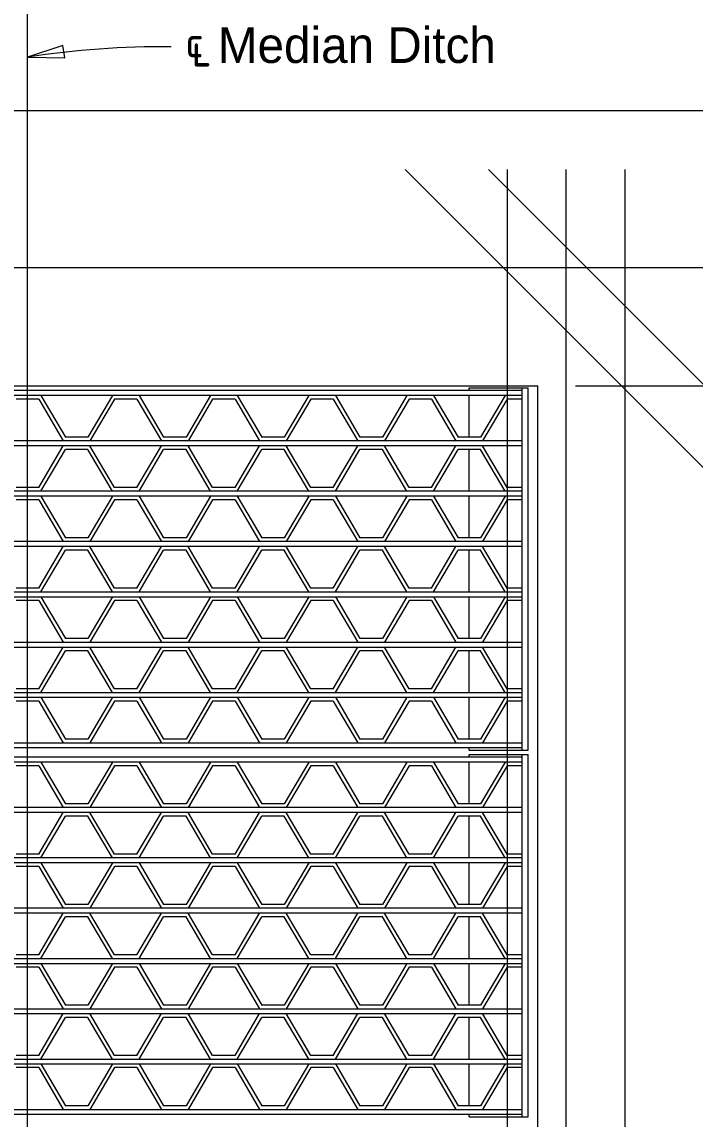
# Model space of a CAD drawing. Extents: x 1.4 to 54.1, y -0.5 to 22.6.
# Drawn here: x 17.123 to 19.98, y 12.044 to 16.698 of the extents above; entities that cross this region are included whole.
import ezdxf

# ---------------------------------------------------------------- set-up
doc = ezdxf.new("R2010")
doc.units = 0
for name, color, linetype in [('AdhocPoint_dp', 7, 'Continuous'), ('CL_Major', 7, 'Continuous'), ('Leader', 7, 'Continuous'), ('PlotBorder_dp', 7, 'Continuous'), ('Rebar', 7, 'Continuous'), ('Rebar_h', 7, 'Continuous'), ('SteelMisc', 7, 'Continuous'), ('WallConc', 7, 'Continuous'), ('WallConc_h', 7, 'Continuous')]:
    doc.layers.add(name, color=color, linetype=linetype)

msp = doc.modelspace()

# ---------------------------------------------------------------- linework, layer by layer
at = {"layer": 'CL_Major'}
msp.add_line((17.1465, 8.8184), (17.1465, 16.8163), dxfattribs=at)
at = {"layer": 'Leader'}
msp.add_arc((17.7214, 12.8798), 3.7133, 89.4708, 98.906, dxfattribs=at)
at = {"layer": 'PlotBorder_dp'}
msp.add_line((19.473, 15.1547), (22.2866, 15.1547), dxfattribs=at)
msp.add_lwpolyline([(17.1465, 16.5483), (17.3049, 16.5463), (17.2967, 16.5986)], close=True, dxfattribs=at)
at = {"layer": 'Rebar'}
for p, q in [((21.2249, 13.5966), (18.7501, 16.0714)), ((21.5785, 13.5966), (19.1036, 16.0714))]:
    msp.add_line(p, q, dxfattribs=at)
at = {"layer": 'Rebar_h'}
for p, q in [((19.1831, 9.1964), (19.1831, 16.0714)), ((19.4331, 9.1964), (19.4331, 16.0714)), ((19.6831, 9.1964), (19.6831, 16.0714))]:
    msp.add_line(p, q, dxfattribs=at)
at = {"layer": 'SteelMisc'}
for p, q in [((19.2455, 15.1346), (15.0476, 15.1346)), ((19.0215, 15.1452), (19.2715, 15.1452)), ((19.0215, 15.1346), (19.0215, 15.1452)), ((19.2455, 13.6087), (19.2455, 15.1452)), ((19.2715, 13.6087), (19.2715, 15.1452)), ((19.2455, 15.1138), (15.0476, 15.1138)), ((17.1941, 15.0982), (17.0989, 15.0982)), ((17.1941, 15.0982), (17.2983, 14.9211)), ((17.2031, 15.1138), (17.3072, 14.9367)), ((17.5067, 15.1138), (17.4025, 14.9367)), ((17.5156, 15.0982), (17.4114, 14.9211)), ((17.6108, 15.0982), (17.5156, 15.0982)), ((17.6108, 15.0982), (17.715, 14.9211)), ((17.6198, 15.1138), (17.7239, 14.9367)), ((17.9234, 15.1138), (17.8192, 14.9367)), ((17.9323, 15.0982), (17.8281, 14.9211)), ((18.0275, 15.0982), (17.9323, 15.0982)), ((18.0275, 15.0982), (18.1317, 14.9211)), ((18.0365, 15.1138), (18.1406, 14.9367)), ((18.3401, 15.1138), (18.2359, 14.9367)), ((18.349, 15.0982), (18.2448, 14.9211)), ((18.4442, 15.0982), (18.349, 15.0982)), ((18.4442, 15.0982), (18.5484, 14.9211)), ((18.4532, 15.1138), (18.5573, 14.9367)), ((18.7568, 15.1138), (18.6526, 14.9367)), ((18.7657, 15.0982), (18.6615, 14.9211)), ((18.8609, 15.0982), (18.7657, 15.0982)), ((18.8609, 15.0982), (18.9651, 14.9211)), ((18.8699, 15.1138), (18.974, 14.9367)), ((19.0215, 14.9367), (19.0215, 15.1138)), ((19.1735, 15.1138), (19.0693, 14.9367)), ((19.1824, 15.0982), (19.0782, 14.9211)), ((19.2455, 15.0982), (19.1824, 15.0982)), ((19.2455, 14.9211), (15.0476, 14.9211)), ((19.2455, 14.9003), (15.0476, 14.9003)), ((17.1941, 14.7232), (17.2983, 14.9003)), ((17.4025, 14.9367), (17.3072, 14.9367)), ((17.5156, 14.7232), (17.4114, 14.9003)), ((17.6108, 14.7232), (17.715, 14.9003)), ((17.8192, 14.9367), (17.7239, 14.9367)), ((17.9323, 14.7232), (17.8281, 14.9003)), ((18.0275, 14.7232), (18.1317, 14.9003)), ((18.2359, 14.9367), (18.1406, 14.9367)), ((18.349, 14.7232), (18.2448, 14.9003)), ((18.4442, 14.7232), (18.5484, 14.9003)), ((18.6526, 14.9367), (18.5573, 14.9367)), ((18.7657, 14.7232), (18.6615, 14.9003)), ((18.8609, 14.7232), (18.9651, 14.9003)), ((19.0693, 14.9367), (18.974, 14.9367)), ((19.1824, 14.7232), (19.0782, 14.9003)), ((17.2031, 14.7076), (17.3072, 14.8847)), ((17.4025, 14.8847), (17.3072, 14.8847)), ((17.5067, 14.7076), (17.4025, 14.8847)), ((17.6198, 14.7076), (17.7239, 14.8847)), ((17.8192, 14.8847), (17.7239, 14.8847)), ((17.9234, 14.7076), (17.8192, 14.8847)), ((18.0365, 14.7076), (18.1406, 14.8847)), ((18.2359, 14.8847), (18.1406, 14.8847)), ((18.3401, 14.7076), (18.2359, 14.8847)), ((18.4532, 14.7076), (18.5573, 14.8847)), ((18.6526, 14.8847), (18.5573, 14.8847)), ((18.7568, 14.7076), (18.6526, 14.8847)), ((18.8699, 14.7076), (18.974, 14.8847)), ((19.0693, 14.8847), (18.974, 14.8847)), ((19.0215, 14.7076), (19.0215, 14.8847)), ((19.1735, 14.7076), (19.0693, 14.8847)), ((17.1941, 14.7232), (17.0989, 14.7232)), ((17.6108, 14.7232), (17.5156, 14.7232)), ((18.0275, 14.7232), (17.9323, 14.7232)), ((18.4442, 14.7232), (18.349, 14.7232)), ((18.8609, 14.7232), (18.7657, 14.7232)), ((19.2455, 14.7232), (19.1824, 14.7232)), ((19.2455, 14.7076), (15.0476, 14.7076)), ((19.2455, 14.6868), (15.0476, 14.6868)), ((17.1941, 14.6712), (17.0989, 14.6712)), ((17.1941, 14.6712), (17.2983, 14.4941)), ((17.2031, 14.6868), (17.3072, 14.5097)), ((17.5067, 14.6868), (17.4025, 14.5097)), ((17.5156, 14.6712), (17.4114, 14.4941)), ((17.6108, 14.6712), (17.5156, 14.6712)), ((17.6108, 14.6712), (17.715, 14.4941)), ((17.6198, 14.6868), (17.7239, 14.5097)), ((17.9234, 14.6868), (17.8192, 14.5097)), ((17.9323, 14.6712), (17.8281, 14.4941)), ((18.0275, 14.6712), (17.9323, 14.6712)), ((18.0275, 14.6712), (18.1317, 14.4941)), ((18.0365, 14.6868), (18.1406, 14.5097)), ((18.3401, 14.6868), (18.2359, 14.5097)), ((18.349, 14.6712), (18.2448, 14.4941)), ((18.4442, 14.6712), (18.349, 14.6712)), ((18.4442, 14.6712), (18.5484, 14.4941)), ((18.4532, 14.6868), (18.5573, 14.5097)), ((18.7568, 14.6868), (18.6526, 14.5097)), ((18.7657, 14.6712), (18.6615, 14.4941)), ((18.8609, 14.6712), (18.7657, 14.6712)), ((18.8609, 14.6712), (18.9651, 14.4941)), ((18.8699, 14.6868), (18.974, 14.5097)), ((19.0215, 14.5097), (19.0215, 14.6868)), ((19.1735, 14.6868), (19.0693, 14.5097)), ((19.1824, 14.6712), (19.0782, 14.4941)), ((19.2455, 14.6712), (19.1824, 14.6712)), ((19.2455, 14.4941), (15.0476, 14.4941)), ((17.4025, 14.5097), (17.3072, 14.5097)), ((17.8192, 14.5097), (17.7239, 14.5097)), ((18.2359, 14.5097), (18.1406, 14.5097)), ((18.6526, 14.5097), (18.5573, 14.5097)), ((19.0693, 14.5097), (18.974, 14.5097)), ((19.2455, 14.4733), (15.0476, 14.4733)), ((17.1941, 14.2962), (17.2983, 14.4733)), ((17.2031, 14.2806), (17.3072, 14.4577)), ((17.4025, 14.4577), (17.3072, 14.4577)), ((17.5067, 14.2806), (17.4025, 14.4577)), ((17.5156, 14.2962), (17.4114, 14.4733)), ((17.6108, 14.2962), (17.715, 14.4733)), ((17.6198, 14.2806), (17.7239, 14.4577)), ((17.8192, 14.4577), (17.7239, 14.4577)), ((17.9234, 14.2806), (17.8192, 14.4577)), ((17.9323, 14.2962), (17.8281, 14.4733)), ((18.0275, 14.2962), (18.1317, 14.4733)), ((18.0365, 14.2806), (18.1406, 14.4577)), ((18.2359, 14.4577), (18.1406, 14.4577)), ((18.3401, 14.2806), (18.2359, 14.4577)), ((18.349, 14.2962), (18.2448, 14.4733)), ((18.4442, 14.2962), (18.5484, 14.4733)), ((18.4532, 14.2806), (18.5573, 14.4577)), ((18.6526, 14.4577), (18.5573, 14.4577)), ((18.7568, 14.2806), (18.6526, 14.4577)), ((18.7657, 14.2962), (18.6615, 14.4733)), ((18.8609, 14.2962), (18.9651, 14.4733)), ((18.8699, 14.2806), (18.974, 14.4577)), ((19.0693, 14.4577), (18.974, 14.4577)), ((19.0215, 14.2806), (19.0215, 14.4577)), ((19.1735, 14.2806), (19.0693, 14.4577)), ((19.1824, 14.2962), (19.0782, 14.4733)), ((17.1941, 14.2962), (17.0989, 14.2962)), ((17.6108, 14.2962), (17.5156, 14.2962)), ((18.0275, 14.2962), (17.9323, 14.2962)), ((18.4442, 14.2962), (18.349, 14.2962)), ((18.8609, 14.2962), (18.7657, 14.2962)), ((19.2455, 14.2962), (19.1824, 14.2962)), ((15.0476, 14.2806), (19.2455, 14.2806)), ((15.0476, 14.2598), (19.2455, 14.2598)), ((17.1941, 14.2442), (17.0989, 14.2442)), ((17.1941, 14.2442), (17.2983, 14.0671)), ((17.2031, 14.2598), (17.3072, 14.0827)), ((17.5067, 14.2598), (17.4025, 14.0827)), ((17.5156, 14.2442), (17.4114, 14.0671)), ((17.6108, 14.2442), (17.5156, 14.2442)), ((17.6108, 14.2442), (17.715, 14.0671)), ((17.6198, 14.2598), (17.7239, 14.0827)), ((17.9234, 14.2598), (17.8192, 14.0827)), ((17.9323, 14.2442), (17.8281, 14.0671)), ((18.0275, 14.2442), (17.9323, 14.2442)), ((18.0275, 14.2442), (18.1317, 14.0671)), ((18.0365, 14.2598), (18.1406, 14.0827)), ((18.3401, 14.2598), (18.2359, 14.0827)), ((18.349, 14.2442), (18.2448, 14.0671)), ((18.4442, 14.2442), (18.349, 14.2442)), ((18.4442, 14.2442), (18.5484, 14.0671)), ((18.4532, 14.2598), (18.5573, 14.0827)), ((18.7568, 14.2598), (18.6526, 14.0827)), ((18.7657, 14.2442), (18.6615, 14.0671)), ((18.8609, 14.2442), (18.7657, 14.2442)), ((18.8609, 14.2442), (18.9651, 14.0671)), ((18.8699, 14.2598), (18.974, 14.0827)), ((19.0215, 14.0827), (19.0215, 14.2598)), ((19.1735, 14.2598), (19.0693, 14.0827)), ((19.1824, 14.2442), (19.0782, 14.0671)), ((19.2455, 14.2442), (19.1824, 14.2442)), ((15.0476, 14.0671), (19.2455, 14.0671)), ((17.4025, 14.0827), (17.3072, 14.0827)), ((17.8192, 14.0827), (17.7239, 14.0827)), ((18.2359, 14.0827), (18.1406, 14.0827)), ((18.6526, 14.0827), (18.5573, 14.0827)), ((19.0693, 14.0827), (18.974, 14.0827)), ((15.0476, 14.0463), (19.2455, 14.0463)), ((17.1941, 13.8692), (17.2983, 14.0463)), ((17.2031, 13.8536), (17.3072, 14.0307)), ((17.4025, 14.0307), (17.3072, 14.0307)), ((17.5067, 13.8536), (17.4025, 14.0307)), ((17.5156, 13.8692), (17.4114, 14.0463)), ((17.6108, 13.8692), (17.715, 14.0463)), ((17.6198, 13.8536), (17.7239, 14.0307)), ((17.8192, 14.0307), (17.7239, 14.0307)), ((17.9234, 13.8536), (17.8192, 14.0307)), ((17.9323, 13.8692), (17.8281, 14.0463)), ((18.0275, 13.8692), (18.1317, 14.0463)), ((18.0365, 13.8536), (18.1406, 14.0307)), ((18.2359, 14.0307), (18.1406, 14.0307)), ((18.3401, 13.8536), (18.2359, 14.0307)), ((18.349, 13.8692), (18.2448, 14.0463)), ((18.4442, 13.8692), (18.5484, 14.0463)), ((18.4532, 13.8536), (18.5573, 14.0307)), ((18.6526, 14.0307), (18.5573, 14.0307)), ((18.7568, 13.8536), (18.6526, 14.0307)), ((18.7657, 13.8692), (18.6615, 14.0463)), ((18.8609, 13.8692), (18.9651, 14.0463)), ((18.8699, 13.8536), (18.974, 14.0307)), ((19.0693, 14.0307), (18.974, 14.0307)), ((19.0215, 13.8536), (19.0215, 14.0307)), ((19.1735, 13.8536), (19.0693, 14.0307)), ((19.1824, 13.8692), (19.0782, 14.0463)), ((15.0476, 13.8536), (19.2455, 13.8536)), ((15.0476, 13.8328), (19.2455, 13.8328)), ((17.1941, 13.8692), (17.0989, 13.8692)), ((17.2031, 13.8328), (17.3072, 13.6557)), ((17.5067, 13.8328), (17.4025, 13.6557)), ((17.6108, 13.8692), (17.5156, 13.8692)), ((17.6198, 13.8328), (17.7239, 13.6557)), ((17.9234, 13.8328), (17.8192, 13.6557)), ((18.0275, 13.8692), (17.9323, 13.8692)), ((18.0365, 13.8328), (18.1406, 13.6557)), ((18.3401, 13.8328), (18.2359, 13.6557)), ((18.4442, 13.8692), (18.349, 13.8692)), ((18.4532, 13.8328), (18.5573, 13.6557)), ((18.7568, 13.8328), (18.6526, 13.6557)), ((18.8609, 13.8692), (18.7657, 13.8692)), ((18.8699, 13.8328), (18.974, 13.6557)), ((19.0215, 13.6557), (19.0215, 13.8328)), ((19.1735, 13.8328), (19.0693, 13.6557)), ((19.2455, 13.8692), (19.1824, 13.8692)), ((17.1941, 13.8172), (17.0989, 13.8172)), ((17.1941, 13.8172), (17.2983, 13.6401)), ((17.5156, 13.8172), (17.4114, 13.6401)), ((17.6108, 13.8172), (17.5156, 13.8172)), ((17.6108, 13.8172), (17.715, 13.6401)), ((17.9323, 13.8172), (17.8281, 13.6401)), ((18.0275, 13.8172), (17.9323, 13.8172)), ((18.0275, 13.8172), (18.1317, 13.6401)), ((18.349, 13.8172), (18.2448, 13.6401)), ((18.4442, 13.8172), (18.349, 13.8172)), ((18.4442, 13.8172), (18.5484, 13.6401)), ((18.7657, 13.8172), (18.6615, 13.6401)), ((18.8609, 13.8172), (18.7657, 13.8172)), ((18.8609, 13.8172), (18.9651, 13.6401)), ((19.1824, 13.8172), (19.0782, 13.6401)), ((19.2455, 13.8172), (19.1824, 13.8172)), ((15.0476, 13.6401), (19.2455, 13.6401)), ((17.4025, 13.6557), (17.3072, 13.6557)), ((17.8192, 13.6557), (17.7239, 13.6557)), ((18.2359, 13.6557), (18.1406, 13.6557)), ((18.6526, 13.6557), (18.5573, 13.6557)), ((19.0693, 13.6557), (18.974, 13.6557)), ((15.0476, 13.6193), (19.2455, 13.6193)), ((19.0215, 13.6087), (19.0215, 13.6193)), ((19.0215, 13.6087), (19.2715, 13.6087)), ((19.2455, 13.5791), (15.0476, 13.5791)), ((19.2455, 13.5583), (15.0476, 13.5583)), ((17.2031, 13.5583), (17.3072, 13.3812)), ((17.5067, 13.5583), (17.4025, 13.3812)), ((17.6198, 13.5583), (17.7239, 13.3812)), ((17.9234, 13.5583), (17.8192, 13.3812)), ((18.0365, 13.5583), (18.1406, 13.3812)), ((18.3401, 13.5583), (18.2359, 13.3812)), ((18.4532, 13.5583), (18.5573, 13.3812)), ((18.7568, 13.5583), (18.6526, 13.3812)), ((18.8699, 13.5583), (18.974, 13.3812)), ((19.0215, 13.5897), (19.2715, 13.5897)), ((19.0215, 13.5791), (19.0215, 13.5897)), ((19.0215, 13.3812), (19.0215, 13.5583)), ((19.1735, 13.5583), (19.0693, 13.3812)), ((19.2455, 12.0532), (19.2455, 13.5897)), ((19.2715, 12.0532), (19.2715, 13.5897)), ((17.1941, 13.5427), (17.0989, 13.5427)), ((17.1941, 13.5427), (17.2983, 13.3656)), ((17.5156, 13.5427), (17.4114, 13.3656)), ((17.6108, 13.5427), (17.5156, 13.5427)), ((17.6108, 13.5427), (17.715, 13.3656)), ((17.9323, 13.5427), (17.8281, 13.3656)), ((18.0275, 13.5427), (17.9323, 13.5427)), ((18.0275, 13.5427), (18.1317, 13.3656)), ((18.349, 13.5427), (18.2448, 13.3656)), ((18.4442, 13.5427), (18.349, 13.5427)), ((18.4442, 13.5427), (18.5484, 13.3656)), ((18.7657, 13.5427), (18.6615, 13.3656)), ((18.8609, 13.5427), (18.7657, 13.5427)), ((18.8609, 13.5427), (18.9651, 13.3656)), ((19.1824, 13.5427), (19.0782, 13.3656)), ((19.2455, 13.5427), (19.1824, 13.5427)), ((19.2455, 13.3656), (15.0476, 13.3656)), ((17.4025, 13.3812), (17.3072, 13.3812)), ((17.8192, 13.3812), (17.7239, 13.3812)), ((18.2359, 13.3812), (18.1406, 13.3812)), ((18.6526, 13.3812), (18.5573, 13.3812)), ((19.0693, 13.3812), (18.974, 13.3812)), ((19.2455, 13.3448), (15.0476, 13.3448)), ((17.1941, 13.1677), (17.2983, 13.3448)), ((17.2031, 13.1521), (17.3072, 13.3292)), ((17.4025, 13.3292), (17.3072, 13.3292)), ((17.5067, 13.1521), (17.4025, 13.3292)), ((17.5156, 13.1677), (17.4114, 13.3448)), ((17.6108, 13.1677), (17.715, 13.3448)), ((17.6198, 13.1521), (17.7239, 13.3292)), ((17.8192, 13.3292), (17.7239, 13.3292)), ((17.9234, 13.1521), (17.8192, 13.3292)), ((17.9323, 13.1677), (17.8281, 13.3448)), ((18.0275, 13.1677), (18.1317, 13.3448)), ((18.0365, 13.1521), (18.1406, 13.3292)), ((18.2359, 13.3292), (18.1406, 13.3292)), ((18.3401, 13.1521), (18.2359, 13.3292)), ((18.349, 13.1677), (18.2448, 13.3448)), ((18.4442, 13.1677), (18.5484, 13.3448)), ((18.4532, 13.1521), (18.5573, 13.3292)), ((18.6526, 13.3292), (18.5573, 13.3292)), ((18.7568, 13.1521), (18.6526, 13.3292)), ((18.7657, 13.1677), (18.6615, 13.3448)), ((18.8609, 13.1677), (18.9651, 13.3448)), ((18.8699, 13.1521), (18.974, 13.3292)), ((19.0693, 13.3292), (18.974, 13.3292)), ((19.0215, 13.1521), (19.0215, 13.3292)), ((19.1735, 13.1521), (19.0693, 13.3292)), ((19.1824, 13.1677), (19.0782, 13.3448)), ((19.2455, 13.1521), (15.0476, 13.1521)), ((19.2455, 13.1313), (15.0476, 13.1313)), ((17.1941, 13.1677), (17.0989, 13.1677)), ((17.2031, 13.1313), (17.3072, 12.9542)), ((17.5067, 13.1313), (17.4025, 12.9542)), ((17.6108, 13.1677), (17.5156, 13.1677)), ((17.6198, 13.1313), (17.7239, 12.9542)), ((17.9234, 13.1313), (17.8192, 12.9542)), ((18.0275, 13.1677), (17.9323, 13.1677)), ((18.0365, 13.1313), (18.1406, 12.9542)), ((18.3401, 13.1313), (18.2359, 12.9542)), ((18.4442, 13.1677), (18.349, 13.1677)), ((18.4532, 13.1313), (18.5573, 12.9542)), ((18.7568, 13.1313), (18.6526, 12.9542)), ((18.8609, 13.1677), (18.7657, 13.1677)), ((18.8699, 13.1313), (18.974, 12.9542)), ((19.0215, 12.9542), (19.0215, 13.1313)), ((19.1735, 13.1313), (19.0693, 12.9542)), ((19.2455, 13.1677), (19.1824, 13.1677)), ((17.1941, 13.1157), (17.0989, 13.1157)), ((17.1941, 13.1157), (17.2983, 12.9386)), ((17.5156, 13.1157), (17.4114, 12.9386)), ((17.6108, 13.1157), (17.5156, 13.1157)), ((17.6108, 13.1157), (17.715, 12.9386)), ((17.9323, 13.1157), (17.8281, 12.9386)), ((18.0275, 13.1157), (17.9323, 13.1157)), ((18.0275, 13.1157), (18.1317, 12.9386)), ((18.349, 13.1157), (18.2448, 12.9386)), ((18.4442, 13.1157), (18.349, 13.1157)), ((18.4442, 13.1157), (18.5484, 12.9386)), ((18.7657, 13.1157), (18.6615, 12.9386)), ((18.8609, 13.1157), (18.7657, 13.1157)), ((18.8609, 13.1157), (18.9651, 12.9386)), ((19.1824, 13.1157), (19.0782, 12.9386)), ((19.2455, 13.1157), (19.1824, 13.1157)), ((17.4025, 12.9542), (17.3072, 12.9542)), ((17.8192, 12.9542), (17.7239, 12.9542)), ((18.2359, 12.9542), (18.1406, 12.9542)), ((18.6526, 12.9542), (18.5573, 12.9542)), ((19.0693, 12.9542), (18.974, 12.9542)), ((19.2455, 12.9386), (15.0476, 12.9386)), ((19.2455, 12.9178), (15.0476, 12.9178)), ((17.1941, 12.7407), (17.2983, 12.9178)), ((17.2031, 12.7251), (17.3072, 12.9022)), ((17.4025, 12.9022), (17.3072, 12.9022)), ((17.5067, 12.7251), (17.4025, 12.9022)), ((17.5156, 12.7407), (17.4114, 12.9178)), ((17.6108, 12.7407), (17.715, 12.9178)), ((17.6198, 12.7251), (17.7239, 12.9022)), ((17.8192, 12.9022), (17.7239, 12.9022)), ((17.9234, 12.7251), (17.8192, 12.9022)), ((17.9323, 12.7407), (17.8281, 12.9178)), ((18.0275, 12.7407), (18.1317, 12.9178)), ((18.0365, 12.7251), (18.1406, 12.9022)), ((18.2359, 12.9022), (18.1406, 12.9022)), ((18.3401, 12.7251), (18.2359, 12.9022)), ((18.349, 12.7407), (18.2448, 12.9178)), ((18.4442, 12.7407), (18.5484, 12.9178)), ((18.4532, 12.7251), (18.5573, 12.9022)), ((18.6526, 12.9022), (18.5573, 12.9022)), ((18.7568, 12.7251), (18.6526, 12.9022)), ((18.7657, 12.7407), (18.6615, 12.9178)), ((18.8609, 12.7407), (18.9651, 12.9178)), ((18.8699, 12.7251), (18.974, 12.9022)), ((19.0693, 12.9022), (18.974, 12.9022)), ((19.0215, 12.7251), (19.0215, 12.9022)), ((19.1735, 12.7251), (19.0693, 12.9022)), ((19.1824, 12.7407), (19.0782, 12.9178)), ((15.0476, 12.7251), (19.2455, 12.7251)), ((17.1941, 12.7407), (17.0989, 12.7407)), ((17.6108, 12.7407), (17.5156, 12.7407)), ((18.0275, 12.7407), (17.9323, 12.7407)), ((18.4442, 12.7407), (18.349, 12.7407)), ((18.8609, 12.7407), (18.7657, 12.7407)), ((19.2455, 12.7407), (19.1824, 12.7407)), ((15.0476, 12.7043), (19.2455, 12.7043)), ((17.1941, 12.6887), (17.0989, 12.6887)), ((17.1941, 12.6887), (17.2983, 12.5116)), ((17.2031, 12.7043), (17.3072, 12.5272)), ((17.5067, 12.7043), (17.4025, 12.5272)), ((17.5156, 12.6887), (17.4114, 12.5116)), ((17.6108, 12.6887), (17.5156, 12.6887)), ((17.6108, 12.6887), (17.715, 12.5116)), ((17.6198, 12.7043), (17.7239, 12.5272)), ((17.9234, 12.7043), (17.8192, 12.5272)), ((17.9323, 12.6887), (17.8281, 12.5116)), ((18.0275, 12.6887), (17.9323, 12.6887)), ((18.0275, 12.6887), (18.1317, 12.5116)), ((18.0365, 12.7043), (18.1406, 12.5272)), ((18.3401, 12.7043), (18.2359, 12.5272)), ((18.349, 12.6887), (18.2448, 12.5116)), ((18.4442, 12.6887), (18.349, 12.6887)), ((18.4442, 12.6887), (18.5484, 12.5116)), ((18.4532, 12.7043), (18.5573, 12.5272)), ((18.7568, 12.7043), (18.6526, 12.5272)), ((18.7657, 12.6887), (18.6615, 12.5116)), ((18.8609, 12.6887), (18.7657, 12.6887)), ((18.8609, 12.6887), (18.9651, 12.5116)), ((18.8699, 12.7043), (18.974, 12.5272)), ((19.0215, 12.5272), (19.0215, 12.7043)), ((19.1735, 12.7043), (19.0693, 12.5272)), ((19.1824, 12.6887), (19.0782, 12.5116)), ((19.2455, 12.6887), (19.1824, 12.6887)), ((17.4025, 12.5272), (17.3072, 12.5272)), ((17.8192, 12.5272), (17.7239, 12.5272)), ((18.2359, 12.5272), (18.1406, 12.5272)), ((18.6526, 12.5272), (18.5573, 12.5272)), ((19.0693, 12.5272), (18.974, 12.5272)), ((15.0476, 12.5116), (19.2455, 12.5116)), ((15.0476, 12.4908), (19.2455, 12.4908)), ((17.1941, 12.3137), (17.2983, 12.4908)), ((17.2031, 12.2981), (17.3072, 12.4752)), ((17.4025, 12.4752), (17.3072, 12.4752)), ((17.5067, 12.2981), (17.4025, 12.4752)), ((17.5156, 12.3137), (17.4114, 12.4908)), ((17.6108, 12.3137), (17.715, 12.4908)), ((17.6198, 12.2981), (17.7239, 12.4752)), ((17.8192, 12.4752), (17.7239, 12.4752)), ((17.9234, 12.2981), (17.8192, 12.4752)), ((17.9323, 12.3137), (17.8281, 12.4908)), ((18.0275, 12.3137), (18.1317, 12.4908)), ((18.0365, 12.2981), (18.1406, 12.4752)), ((18.2359, 12.4752), (18.1406, 12.4752)), ((18.3401, 12.2981), (18.2359, 12.4752)), ((18.349, 12.3137), (18.2448, 12.4908)), ((18.4442, 12.3137), (18.5484, 12.4908)), ((18.4532, 12.2981), (18.5573, 12.4752)), ((18.6526, 12.4752), (18.5573, 12.4752)), ((18.7568, 12.2981), (18.6526, 12.4752)), ((18.7657, 12.3137), (18.6615, 12.4908)), ((18.8609, 12.3137), (18.9651, 12.4908)), ((18.8699, 12.2981), (18.974, 12.4752)), ((19.0693, 12.4752), (18.974, 12.4752)), ((19.0215, 12.2981), (19.0215, 12.4752)), ((19.1735, 12.2981), (19.0693, 12.4752)), ((19.1824, 12.3137), (19.0782, 12.4908)), ((15.0476, 12.2981), (19.2455, 12.2981)), ((17.1941, 12.3137), (17.0989, 12.3137)), ((17.6108, 12.3137), (17.5156, 12.3137)), ((18.0275, 12.3137), (17.9323, 12.3137)), ((18.4442, 12.3137), (18.349, 12.3137)), ((18.8609, 12.3137), (18.7657, 12.3137)), ((19.2455, 12.3137), (19.1824, 12.3137)), ((15.0476, 12.2773), (19.2455, 12.2773)), ((17.1941, 12.2617), (17.0989, 12.2617)), ((17.1941, 12.2617), (17.2983, 12.0846)), ((17.2031, 12.2773), (17.3072, 12.1002)), ((17.5067, 12.2773), (17.4025, 12.1002)), ((17.5156, 12.2617), (17.4114, 12.0846)), ((17.6108, 12.2617), (17.5156, 12.2617)), ((17.6108, 12.2617), (17.715, 12.0846)), ((17.6198, 12.2773), (17.7239, 12.1002)), ((17.9234, 12.2773), (17.8192, 12.1002)), ((17.9323, 12.2617), (17.8281, 12.0846)), ((18.0275, 12.2617), (17.9323, 12.2617)), ((18.0275, 12.2617), (18.1317, 12.0846)), ((18.0365, 12.2773), (18.1406, 12.1002)), ((18.3401, 12.2773), (18.2359, 12.1002)), ((18.349, 12.2617), (18.2448, 12.0846)), ((18.4442, 12.2617), (18.349, 12.2617)), ((18.4442, 12.2617), (18.5484, 12.0846)), ((18.4532, 12.2773), (18.5573, 12.1002)), ((18.7568, 12.2773), (18.6526, 12.1002)), ((18.7657, 12.2617), (18.6615, 12.0846)), ((18.8609, 12.2617), (18.7657, 12.2617)), ((18.8609, 12.2617), (18.9651, 12.0846)), ((18.8699, 12.2773), (18.974, 12.1002)), ((19.0215, 12.1002), (19.0215, 12.2773)), ((19.1735, 12.2773), (19.0693, 12.1002)), ((19.1824, 12.2617), (19.0782, 12.0846)), ((19.2455, 12.2617), (19.1824, 12.2617)), ((15.0476, 12.0846), (19.2455, 12.0846)), ((15.0476, 12.0638), (19.2455, 12.0638)), ((17.4025, 12.1002), (17.3072, 12.1002)), ((17.8192, 12.1002), (17.7239, 12.1002)), ((18.2359, 12.1002), (18.1406, 12.1002)), ((18.6526, 12.1002), (18.5573, 12.1002)), ((19.0693, 12.1002), (18.974, 12.1002)), ((19.0215, 12.0532), (19.0215, 12.0638)), ((19.0215, 12.0532), (19.2715, 12.0532))]:
    msp.add_line(p, q, dxfattribs=at)
at = {"layer": 'WallConc'}
for p, q in [((21.6229, 16.3214), (12.6701, 16.3214)), ((14.9798, 15.1547), (19.3132, 15.1547)), ((19.3132, 10.4881), (19.3132, 15.1547))]:
    msp.add_line(p, q, dxfattribs=at)
at = {"layer": 'WallConc_h'}
msp.add_line((21.6229, 15.6547), (12.6701, 15.6547), dxfattribs=at)

# ---------------------------------------------------------------- texts
at = {"layer": 'AdhocPoint_dp'}
msp.add_text('℄ Median Ditch', height=0.1512, dxfattribs=at).set_placement((17.8161, 16.5241))

doc.saveas('drawing.dxf')
